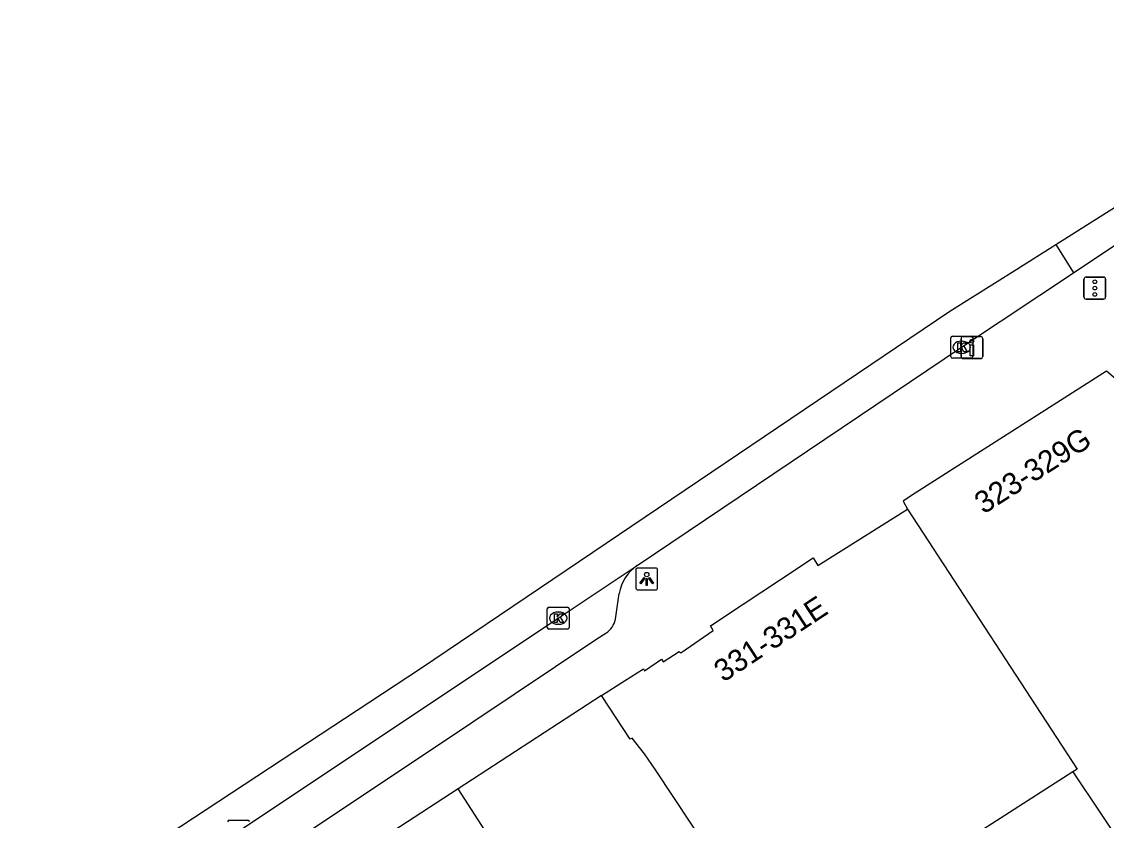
# Model space of a CAD drawing. Extents: x 159822 to 160765, y 380693 to 381634.
# Drawn here: x 160094.7 to 160144.16, y 381587.92 to 381624.35 of the extents above; entities that cross this region are included whole.
import ezdxf

# ---------------------------------------------------------------- set-up
doc = ezdxf.new("R2010")
doc.units = 0
for name, color, linetype in [('IMGEO_Drukknoppaal', 7, 'Continuous'), ('IMGEO_Erf', 7, 'Continuous'), ('IMGEO_Kolk', 7, 'Continuous'), ('IMGEO_Lichtpunt', 7, 'Continuous'), ('IMGEO_Pand', 7, 'Continuous'), ('IMGEO_Pand_nummerreeks', 7, 'Continuous'), ('IMGEO_Rijbaan_lokaal_gesloten', 7, 'Continuous'), ('IMGEO_Verkeersregelinstallatiepaal', 7, 'Continuous'), ('IMGEO_Voetpad_open', 7, 'Continuous')]:
    doc.layers.add(name, color=color, linetype=linetype)

msp = doc.modelspace()

# ---------------------------------------------------------------- linework, layer by layer
at = {"layer": 'IMGEO_Drukknoppaal'}
for p, q in [((160137.533, 381609.081), (160137.533, 381609.881)), ((160137.533, 381609.881), (160137.533, 381609.081)), ((160137.633, 381609.981), (160138.423, 381609.981)), ((160138.423, 381609.981), (160137.633, 381609.981)), ((160138.523, 381609.881), (160138.523, 381609.081)), ((160138.523, 381609.081), (160138.523, 381609.881)), ((160138.423, 381608.981), (160137.633, 381608.981)), ((160137.633, 381608.981), (160138.423, 381608.981))]:
    msp.add_line(p, q, dxfattribs=at)
msp.add_lwpolyline([(160138.103, 381609.606), (160138.103, 381609.106), (160137.953, 381609.106), (160137.953, 381609.606), (160138.103, 381609.606)], dxfattribs=at)
msp.add_circle((160138.028, 381609.771), 0.085, dxfattribs=at)
for centre, start, end in [((160137.633, 381609.881), 90, 180), ((160137.633, 381609.881), 90, 180), ((160138.423, 381609.881), 0, 90), ((160138.423, 381609.881), 360, 90), ((160137.633, 381609.081), 180, 270), ((160137.633, 381609.081), 180, 270), ((160138.423, 381609.081), 270, 0), ((160138.423, 381609.081), 270, 0)]:
    msp.add_arc(centre, 0.1, start, end, dxfattribs=at)
at = {"layer": 'IMGEO_Erf'}
msp.add_lwpolyline([(160116.124, 381586.992), (160114.609, 381589.36)], dxfattribs=at)
at = {"layer": 'IMGEO_Kolk'}
for p, q in [((160137.066, 381609.069), (160137.066, 381609.921)), ((160137.141, 381609.995), (160137.993, 381609.995)), ((160137.554, 381609.775), (160137.579, 381609.775)), ((160138.067, 381609.921), (160138.067, 381609.069)), ((160137.577, 381609.215), (160137.552, 381609.215)), ((160137.993, 381608.995), (160137.141, 381608.995)), ((160118.667, 381596.713), (160118.667, 381597.565)), ((160118.742, 381597.639), (160119.594, 381597.639)), ((160119.155, 381597.419), (160119.18, 381597.419)), ((160119.668, 381597.565), (160119.668, 381596.713)), ((160119.178, 381596.859), (160119.153, 381596.859)), ((160119.594, 381596.639), (160118.742, 381596.639)), ((160104.162, 381587.918), (160105.014, 381587.918))]:
    msp.add_line(p, q, dxfattribs=at)
for points in [[(160137.066, 381609.069), (160137.066, 381609.921)], [(160137.141, 381609.995), (160137.993, 381609.995)], [(160137.387, 381609.695), (160137.51, 381609.695), (160137.51, 381609.544), (160137.64, 381609.695), (160137.804, 381609.695), (160137.658, 381609.544), (160137.811, 381609.295), (160137.659, 381609.295), (160137.574, 381609.459), (160137.51, 381609.392), (160137.51, 381609.295), (160137.387, 381609.295), (160137.387, 381609.695)], [(160138.067, 381609.921), (160138.067, 381609.069)], [(160137.993, 381608.995), (160137.141, 381608.995)], [(160118.667, 381596.713), (160118.667, 381597.565)], [(160118.742, 381597.639), (160119.594, 381597.639)], [(160118.988, 381597.339), (160119.111, 381597.339), (160119.111, 381597.188), (160119.241, 381597.339), (160119.405, 381597.339), (160119.259, 381597.188), (160119.412, 381596.939), (160119.26, 381596.939), (160119.175, 381597.103), (160119.111, 381597.036), (160119.111, 381596.939), (160118.988, 381596.939), (160118.988, 381597.339)], [(160119.668, 381597.565), (160119.668, 381596.713)], [(160119.594, 381596.639), (160118.742, 381596.639)], [(160104.162, 381587.918), (160105.014, 381587.918)]]:
    msp.add_lwpolyline(points, dxfattribs=at)
for centre, start, end in [((160137.143, 381609.919), 91.552, 178.448), ((160137.143, 381609.919), 91.552, 178.448), ((160137.991, 381609.919), 1.552, 88.448), ((160137.991, 381609.919), 1.552, 88.448), ((160137.143, 381609.071), 181.552, 268.448), ((160137.143, 381609.071), 181.552, 268.448), ((160137.991, 381609.071), 271.552, 358.448), ((160137.991, 381609.071), 271.552, 358.448), ((160118.744, 381597.563), 91.552, 178.448), ((160118.744, 381597.563), 91.552, 178.448), ((160119.592, 381597.563), 1.552, 88.448), ((160119.592, 381597.563), 1.552, 88.448), ((160118.744, 381596.715), 181.552, 268.448), ((160118.744, 381596.715), 181.552, 268.448), ((160119.592, 381596.715), 271.552, 358.448), ((160119.592, 381596.715), 271.552, 358.448), ((160104.164, 381587.842), 91.552, 178.448), ((160104.164, 381587.842), 91.552, 178.448), ((160105.012, 381587.842), 1.552, 88.448), ((160105.012, 381587.842), 1.552, 88.448)]:
    msp.add_arc(centre, 0.0765, start, end, dxfattribs=at)
for centre, major_axis, ratio, start_param, end_param in [((160137.553, 381609.495), (-0.387, 0.002), 0.722429, 4.712389, 7.853982), ((160137.578, 381609.495), (-0.39, 0.002), 0.717154, 1.570796, 4.712389), ((160119.154, 381597.139), (-0.387, 0.002), 0.722429, 4.712389, 7.853982), ((160119.179, 381597.139), (-0.39, 0.002), 0.717154, 1.570796, 4.712389)]:
    msp.add_ellipse(centre, major_axis=major_axis, ratio=ratio, start_param=start_param, end_param=end_param, dxfattribs=at)
at = {"layer": 'IMGEO_Lichtpunt'}
for p, q in [((160122.703, 381599.332), (160122.703, 381598.525)), ((160122.703, 381599.332), (160122.703, 381598.525)), ((160123.605, 381599.427), (160122.797, 381599.427)), ((160123.605, 381599.427), (160122.797, 381599.427)), ((160123.699, 381598.525), (160123.699, 381599.332)), ((160123.699, 381598.525), (160123.699, 381599.332)), ((160122.797, 381598.431), (160123.605, 381598.431)), ((160122.797, 381598.431), (160123.605, 381598.431))]:
    msp.add_line(p, q, dxfattribs=at)
for points in [[(160123.077, 381598.996), (160123.116, 381598.968), (160122.928, 381598.706), (160122.89, 381598.733), (160123.077, 381598.996)], [(160123.179, 381598.948), (160123.226, 381598.948), (160123.226, 381598.626), (160123.179, 381598.626), (160123.179, 381598.948)], [(160123.289, 381598.968), (160123.327, 381598.995), (160123.514, 381598.733), (160123.475, 381598.705), (160123.289, 381598.968)]]:
    msp.add_lwpolyline(points, dxfattribs=at)
msp.add_circle((160123.202, 381599.13), 0.0994, dxfattribs=at)
for centre, start, end in [((160122.797, 381599.332), 90, 180), ((160122.797, 381599.332), 90, 180), ((160123.605, 381599.332), 0, 90), ((160123.605, 381599.332), 0, 90), ((160122.797, 381598.525), 180, 270), ((160122.797, 381598.525), 180, 270), ((160123.605, 381598.525), 270, 0), ((160123.605, 381598.525), 270, 360)]:
    msp.add_arc(centre, 0.0946, start, end, dxfattribs=at)
at = {"layer": 'IMGEO_Pand'}
for points in [[(160151.001, 381611.744), (160150.668, 381611.223), (160146.505, 381606.408), (160144.166, 381608.406), (160135.277, 381602.727), (160134.889, 381602.479), (160135.093, 381602.111)], [(160121.138, 381593.613), (160122.194, 381594.287), (160123.051, 381594.835), (160123.094, 381594.733), (160123.875, 381595.267), (160123.949, 381595.154), (160124.682, 381595.626), (160124.761, 381595.553), (160126.236, 381596.583), (160126.113, 381596.788), (160127.599, 381597.773), (160129.295, 381598.897), (160130.786, 381599.885), (160131.005, 381599.538), (160135.093, 381602.111)], [(160135.093, 381602.111), (160142.83, 381590.253), (160142.628, 381590.123)], [(160129.325, 381581.569), (160123.597, 381590.221), (160123.097, 381590.949), (160122.537, 381591.673), (160122.44, 381591.627), (160121.138, 381593.613)], [(160142.628, 381590.123), (160135.845, 381585.761)], [(160142.628, 381590.123), (160150.202, 381578.819)]]:
    msp.add_lwpolyline(points, dxfattribs=at)
at = {"layer": 'IMGEO_Rijbaan_lokaal_gesloten'}
for points in [[(160141.863, 381614.189), (160156.742, 381623.575), (160157.945, 381624.347)], [(160004.479, 381524.903), (160007.612, 381526.743), (160029.796, 381540.829), (160053.944, 381556.307), (160082.43, 381574.817), (160112.881, 381594.842), (160137.027, 381611.139), (160140.076, 381613.062), (160141.863, 381614.189)], [(160141.863, 381614.189), (160142.662, 381612.896)], [(160142.662, 381612.896), (160144.914, 381614.397)], [(160122.767, 381599.539), (160137.563, 381609.496), (160141.123, 381611.87), (160142.662, 381612.896)], [(160046.466, 381549.511), (160049.671, 381551.552), (160068.295, 381563.576), (160086.868, 381575.798), (160104.583, 381587.419), (160119.163, 381597.14), (160122.767, 381599.539)]]:
    msp.add_lwpolyline(points, dxfattribs=at)
at = {"layer": 'IMGEO_Verkeersregelinstallatiepaal'}
for p, q in [((160143.24, 381612.695), (160144.03, 381612.695)), ((160144.03, 381612.695), (160143.24, 381612.695)), ((160143.14, 381611.795), (160143.14, 381612.595)), ((160143.14, 381612.595), (160143.14, 381611.795)), ((160144.13, 381612.595), (160144.13, 381611.795)), ((160144.13, 381611.795), (160144.13, 381612.595)), ((160144.03, 381611.695), (160143.24, 381611.695)), ((160143.24, 381611.695), (160144.03, 381611.695))]:
    msp.add_line(p, q, dxfattribs=at)
for centre in [(160143.635, 381612.485), (160143.635, 381612.195), (160143.635, 381611.905)]:
    msp.add_circle(centre, 0.085, dxfattribs=at)
for centre, start, end in [((160143.24, 381612.595), 90, 180), ((160143.24, 381612.595), 90, 180), ((160144.03, 381612.595), 0, 90), ((160144.03, 381612.595), 360, 90), ((160143.24, 381611.795), 180, 270), ((160143.24, 381611.795), 180, 270), ((160144.03, 381611.795), 270, 0), ((160144.03, 381611.795), 270, 0)]:
    msp.add_arc(centre, 0.1, start, end, dxfattribs=at)
at = {"layer": 'IMGEO_Voetpad_open'}
for points in [[(160121.778, 381597.09), (160121.948, 381598.26)], [(160050.028, 381549.673), (160059.297, 381555.627), (160101.271, 381583.115), (160104.638, 381585.323), (160113.384, 381591.146), (160120.932, 381596.202), (160121.34, 381596.46)], [(160121.138, 381593.613), (160114.609, 381589.36)], [(160114.609, 381589.36), (160101.301, 381580.69)]]:
    msp.add_lwpolyline(points, dxfattribs=at)
for centre, radius, start, end in [((160123.836, 381597.952), 1.913, 123.9824, 170.7511), ((160120.804, 381597.3), 0.996, 302.5388, 347.8442)]:
    msp.add_arc(centre, radius, start, end, dxfattribs=at)

# ---------------------------------------------------------------- texts
at = {"layer": 'IMGEO_Pand_nummerreeks'}
for s, rotation, p in [('323-329G', 32.5727, (160138.564, 381601.86)), ('331-331E', 33.3404, (160126.696, 381594.191))]:
    msp.add_text(s, height=1, rotation=rotation, dxfattribs=at).set_placement(p)

doc.saveas('drawing.dxf')
